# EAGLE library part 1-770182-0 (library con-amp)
MINI UNIVERSAL MATE-N-LOCK (TM) Vertical 9 Pol. Source: http://catalog.tycoelectronics.com .. ENG_CD_770182_L.pdf
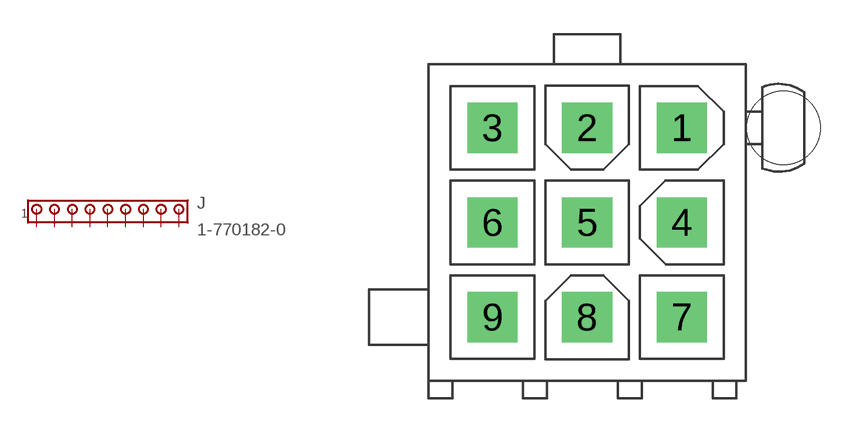
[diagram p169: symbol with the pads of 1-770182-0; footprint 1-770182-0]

Designator prefix J

## 1-770182-0 (MF: TYCO ELECTRONICS; MPN: 1-770182-0; OC_FARNELL: 1098529; OC_NEWARK: 52K3350)  [1-770182-0]
1  1  pas
2  2  pas
3  3  pas
4  4  pas
5  5  pas
6  6  pas
7  7  pas
8  8  pas
9  9  pas

## Footprint 1-770182-0 (pad centres in mm)
MINI UNIVERSAL MATE-N-LOCK (TM) Vertical 9 Pol. Source: http://catalog.tycoelectronics.com .. ENG_CD_770182_L.pdf
drill 1.4 pad 2.2 square: 1 4.14,4.14; 2 0,4.14; 3 -4.14,4.14; 4 4.14,0; 5 0,0; 6 -4.14,0; 7 4.14,-4.14; 8 0,-4.14; 9 -4.14,-4.14
hole 3.2 at 8.59,4.14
